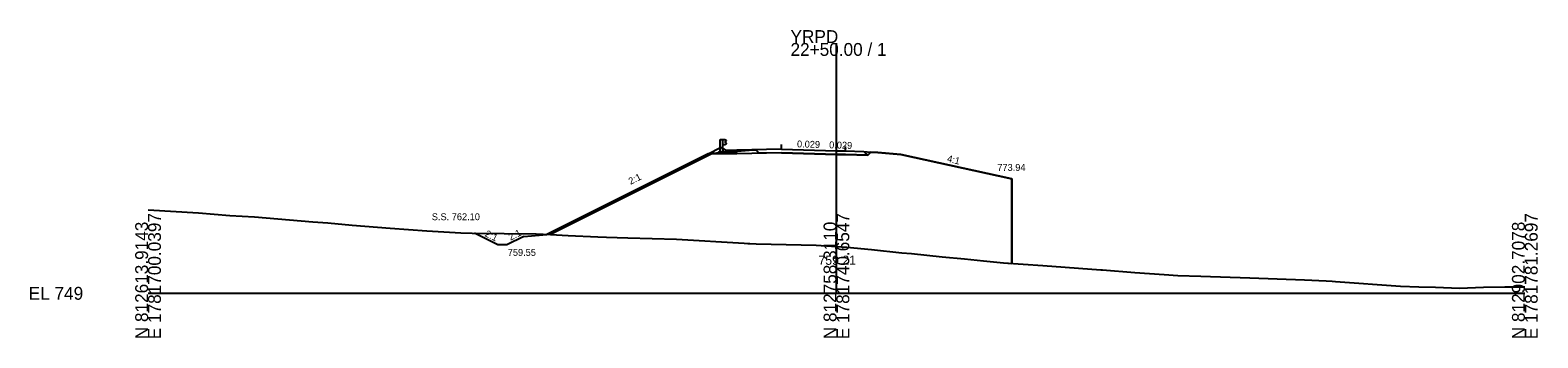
# Model space of a CAD drawing. Extents: x -26 to 1403, y -10 to 9544.
# Drawn here: x 974.3 to 1302.8, y 2490.3 to 2557.3 of the extents above; entities that cross this region are included whole.
import ezdxf

# ---------------------------------------------------------------- set-up
doc = ezdxf.new("R2010")
doc.units = 0
for name, color, linetype in [('Exist Cross Section Cell', 7, 'Continuous'), ('Exist XS Center Line Elevation Label', 7, 'Continuous'), ('Exist XS Ground Line', 7, 'Continuous'), ('Prop XS DDE', 7, 'Continuous'), ('Prop XS Ditch Standard Text', 7, 'Continuous'), ('Prop XS Dump Level', 7, 'Continuous'), ('Prop XS Earthwork Shape', 7, 'Continuous'), ('Prop XS EOT Tick Mark', 7, 'Continuous'), ('Prop XS Finish Grade', 7, 'Continuous'), ('Prop XS Finish Grade CurbGutter', 7, 'Continuous'), ('Prop XS Finish Grade Earthwork', 7, 'Continuous'), ('Prop XS Finish Grade Paved Shoulder', 7, 'Continuous'), ('Prop XS Finish Grade Pavement', 7, 'Continuous'), ('Prop XS Guardrail', 7, 'Continuous'), ('Prop XS Pvmt Edge Slope', 7, 'Continuous'), ('Prop XS SE Text', 7, 'Continuous'), ('Prop XS Side Slope Text', 7, 'Continuous'), ('Prop XS SS Elevation Text', 7, 'Continuous'), ('Prop XS Subgrade CurbGutter', 7, 'Continuous'), ('Prop XS Subgrade Earthwork', 7, 'Continuous')]:
    doc.layers.add(name, color=color, linetype=linetype)

msp = doc.modelspace()

# ---------------------------------------------------------------- linework, layer by layer
at = {"layer": 'Exist Cross Section Cell'}
for p, q in [((1150, 2500), (1150, 2554.52)), ((1000, 2500), (1150, 2500)), ((1150, 2500), (1300, 2500))]:
    msp.add_line(p, q, dxfattribs=at)
at = {"layer": 'Exist XS Ground Line'}
for p, q in [((1000, 2518.17), (1011.02, 2517.5)), ((1011.02, 2517.5), (1017.84, 2516.93)), ((1017.84, 2516.93), (1023.2, 2516.63)), ((1023.2, 2516.63), (1035.93, 2515.6)), ((1035.93, 2515.6), (1039.17, 2515.33)), ((1039.17, 2515.33), (1044.45, 2514.82)), ((1044.45, 2514.82), (1052.79, 2514.17)), ((1052.79, 2514.17), (1060.77, 2513.61)), ((1060.77, 2513.61), (1068.19, 2513.19)), ((1068.19, 2513.19), (1070.64, 2513.1)), ((1070.64, 2513.1), (1084.59, 2512.93)), ((1084.59, 2512.93), (1087.72, 2512.79)), ((1087.72, 2512.79), (1091.53, 2512.59)), ((1091.53, 2512.59), (1098.03, 2512.31)), ((1098.03, 2512.31), (1099.86, 2512.23)), ((1099.86, 2512.23), (1104.54, 2512.1)), ((1104.54, 2512.1), (1115.16, 2511.81)), ((1115.16, 2511.81), (1129.87, 2510.92)), ((1129.87, 2510.92), (1130.67, 2510.88)), ((1130.67, 2510.88), (1131.15, 2510.85)), ((1131.15, 2510.85), (1132.52, 2510.79)), ((1132.52, 2510.79), (1145.57, 2510.52)), ((1145.57, 2510.52), (1150, 2510.21)), ((1150, 2510.21), (1152.27, 2510.05)), ((1152.27, 2510.05), (1157.65, 2509.52)), ((1157.65, 2509.52), (1164.23, 2508.82)), ((1164.23, 2508.82), (1166.34, 2508.66)), ((1166.34, 2508.66), (1173.04, 2507.96)), ((1173.04, 2507.96), (1177.9, 2507.52)), ((1177.9, 2507.52), (1182.08, 2507.06)), ((1182.08, 2507.06), (1186.37, 2506.63)), ((1186.37, 2506.63), (1194.94, 2506.03)), ((1194.94, 2506.03), (1207.61, 2505.13)), ((1207.61, 2505.13), (1207.98, 2505.1)), ((1207.98, 2505.1), (1215.04, 2504.55)), ((1215.04, 2504.55), (1221.44, 2504.07)), ((1221.44, 2504.07), (1224.4, 2503.89)), ((1224.4, 2503.89), (1229.43, 2503.75)), ((1229.43, 2503.75), (1240.05, 2503.38)), ((1240.05, 2503.38), (1251.97, 2502.94)), ((1251.97, 2502.94), (1256.7, 2502.7)), ((1256.7, 2502.7), (1258.04, 2502.65)), ((1258.04, 2502.65), (1258.77, 2502.61)), ((1258.77, 2502.61), (1272.89, 2501.56)), ((1272.89, 2501.56), (1276.9, 2501.42)), ((1276.9, 2501.42), (1280.53, 2501.32)), ((1280.53, 2501.32), (1285.77, 2501.12)), ((1285.77, 2501.12), (1290.98, 2501.37)), ((1290.98, 2501.37), (1295.62, 2501.39)), ((1295.62, 2501.39), (1300, 2501.4))]:
    msp.add_line(p, q, dxfattribs=at)
at = {"layer": 'Prop XS DDE'}
for p, q in [((1076.19, 2510.55), (1071.1, 2513.1)), ((1078.19, 2510.55), (1076.19, 2510.55)), ((1081.9, 2512.41), (1078.19, 2510.55)), ((1081.9, 2512.41), (1086.9, 2512.83))]:
    msp.add_line(p, q, dxfattribs=at)
at = {"layer": 'Prop XS Dump Level'}
for p, q in [((1138, 2531.4), (1150, 2531.05)), ((1150, 2531.05), (1152, 2531))]:
    msp.add_line(p, q, dxfattribs=at)
at = {"layer": 'Prop XS Earthwork Shape'}
msp.add_lwpolyline([(1130.67, 2510.88), (1131.15, 2510.85), (1132.52, 2510.79), (1145.57, 2510.52), (1150, 2510.21), (1152.27, 2510.05), (1157.65, 2509.52), (1164.23, 2508.82), (1166.34, 2508.66), (1173.04, 2507.96), (1177.9, 2507.52), (1182.08, 2507.06), (1186.37, 2506.63), (1188.2, 2506.5), (1188.2, 2524.94), (1164, 2530.24), (1159, 2530.64), (1157.51, 2530.76), (1156.82, 2530.07), (1151.98, 2530.21), (1149.98, 2530.26), (1138, 2530.6), (1133.19, 2530.51), (1132.5, 2531.2), (1131, 2531.08), (1123, 2530.44), (1087.71, 2512.79), (1091.53, 2512.59), (1098.03, 2512.31), (1099.86, 2512.23), (1104.54, 2512.1), (1115.16, 2511.81), (1129.87, 2510.92)], close=True, dxfattribs=at)
at = {"layer": 'Prop XS EOT Tick Mark'}
for p, q in [((1138, 2531.4), (1138, 2532.4)), ((1152, 2531), (1152, 2532))]:
    msp.add_line(p, q, dxfattribs=at)
at = {"layer": 'Prop XS Finish Grade'}
for p, q in [((1122.07, 2530.41), (1124.73, 2531.74)), ((1125.31, 2531.45), (1124.73, 2531.74)), ((1156, 2530.88), (1157.51, 2530.76))]:
    msp.add_line(p, q, dxfattribs=at)
at = {"layer": 'Prop XS Finish Grade CurbGutter'}
for p, q in [((1126, 2531.11), (1125.31, 2531.45)), ((1128.33, 2531.2), (1126, 2531.11))]:
    msp.add_line(p, q, dxfattribs=at)
at = {"layer": 'Prop XS Finish Grade Earthwork'}
for p, q in [((1122.07, 2530.41), (1086.9, 2512.83)), ((1157.51, 2530.76), (1159, 2530.64)), ((1159, 2530.64), (1164, 2530.24)), ((1164, 2530.24), (1188.2, 2524.94)), ((1188.2, 2524.94), (1188.2, 2506.5))]:
    msp.add_line(p, q, dxfattribs=at)
at = {"layer": 'Prop XS Finish Grade Paved Shoulder'}
for p, q in [((1138, 2531.4), (1128.33, 2531.2)), ((1152, 2531), (1156, 2530.88))]:
    msp.add_line(p, q, dxfattribs=at)
at = {"layer": 'Prop XS Finish Grade Pavement'}
for p, q in [((1138, 2531.4), (1150, 2531.05)), ((1150, 2531.05), (1152, 2531))]:
    msp.add_line(p, q, dxfattribs=at)
at = {"layer": 'Prop XS Guardrail'}
for p, q in [((1124.68, 2533.5), (1125.18, 2533.5)), ((1124.68, 2531), (1124.68, 2533.5)), ((1125.18, 2533.5), (1125.68, 2533.5)), ((1125.18, 2533.5), (1125.18, 2531)), ((1125.68, 2533.5), (1125.97, 2533.3)), ((1125.97, 2533.18), (1125.68, 2532.98)), ((1125.97, 2533.3), (1126, 2533.24)), ((1126, 2533.24), (1125.97, 2533.18)), ((1125.68, 2532.37), (1125.18, 2532.37)), ((1125.68, 2532.98), (1125.68, 2532.89)), ((1125.68, 2532.89), (1125.97, 2532.69)), ((1125.97, 2532.57), (1125.68, 2532.37)), ((1125.97, 2532.69), (1126, 2532.63)), ((1126, 2532.63), (1125.97, 2532.57))]:
    msp.add_line(p, q, dxfattribs=at)
at = {"layer": 'Prop XS Pvmt Edge Slope'}
for p, q in [((1124.31, 2530.78), (1123.94, 2530.41)), ((1125.31, 2530.78), (1124.31, 2530.78)), ((1156, 2530.88), (1156.82, 2530.07))]:
    msp.add_line(p, q, dxfattribs=at)
at = {"layer": 'Prop XS Subgrade CurbGutter'}
for p, q in [((1125.31, 2530.78), (1125.31, 2531.45)), ((1128.33, 2530.78), (1125.31, 2530.78)), ((1128.33, 2531.2), (1128.33, 2530.78))]:
    msp.add_line(p, q, dxfattribs=at)
at = {"layer": 'Prop XS Subgrade Earthwork'}
for p, q in [((1123.94, 2530.41), (1122.07, 2530.41)), ((1128.33, 2530.41), (1123.94, 2530.41)), ((1138, 2530.6), (1128.33, 2530.41)), ((1128.33, 2530.41), (1128.33, 2530.41)), ((1138, 2530.6), (1149.98, 2530.26)), ((1149.98, 2530.26), (1151.98, 2530.21)), ((1151.98, 2530.21), (1156.82, 2530.07)), ((1156.82, 2530.07), (1157.51, 2530.76))]:
    msp.add_line(p, q, dxfattribs=at)

# ---------------------------------------------------------------- texts
at = {"layer": 'Exist Cross Section Cell'}
for s, p in [('YRPD', (1140, 2554.52)), ('22+50.00 / 1', (1140, 2551.72)), ('EL 749', (974, 2498.6))]:
    msp.add_text(s, height=2.8, dxfattribs=at).set_placement(p)
for s, p in [('E 1781700.0397', (1002.8, 2490)), ('E 1781740.6547', (1152.8, 2490)), ('E 1781781.2697', (1302.8, 2490)), ('N 812613.9143', (1000, 2490)), ('N 812758.3110', (1150, 2490)), ('N 812902.7078', (1300, 2490))]:
    msp.add_text(s, height=2.8, rotation=90, dxfattribs=at).set_placement(p)
at = {"layer": 'Exist XS Center Line Elevation Label'}
msp.add_text('759.21', height=2, dxfattribs=at).set_placement((1146.08, 2506.21))
at = {"layer": 'Prop XS Ditch Standard Text'}
for s, p in [('773.94', (1185.06, 2526.67)), ('759.55', (1078.38, 2508.16))]:
    msp.add_text(s, height=1.5, dxfattribs=at).set_placement(p)
at = {"layer": 'Prop XS Dump Level'}
for s, p in [('Case4', (1126, 2530.64)), ('Case2', (1128.33, 2531.16)), ('Case4', (1164, 2530.2))]:
    msp.add_text(s, height=0.04, dxfattribs=at).set_placement(p)
at = {"layer": 'Prop XS SE Text'}
for p in [(1141.39, 2531.8), (1148.39, 2531.6)]:
    msp.add_text('0.029', height=1.5, rotation=358.3666, dxfattribs=at).set_placement(p)
at = {"layer": 'Prop XS Side Slope Text'}
for s, rotation, p in [('4:1', 345.9638, (1174, 2528.7)), ('2:1', 26.5651, (1105.15, 2523.62)), ('2:1', 333.4349, (1073.24, 2512.51)), ('2:1', 26.5651, (1078.98, 2511.45))]:
    msp.add_text(s, height=1.5, rotation=rotation, dxfattribs=at).set_placement(p)
at = {"layer": 'Prop XS SS Elevation Text'}
msp.add_text('S.S. 762.10', height=1.5, dxfattribs=at).set_placement((1061.83, 2515.93))

doc.saveas('drawing.dxf')
